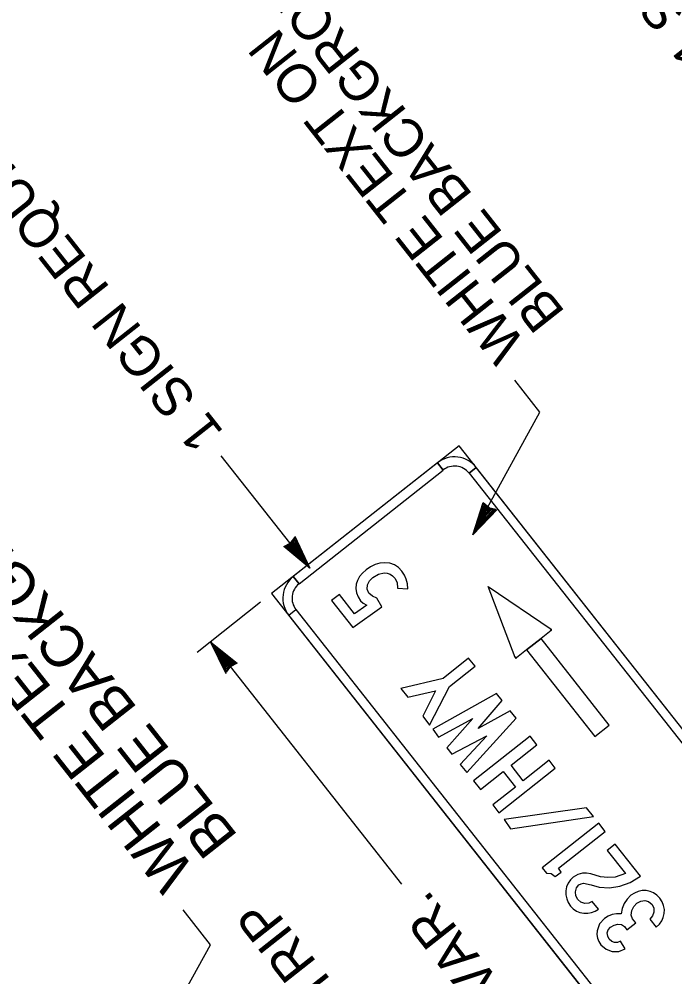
# Model space of a CAD drawing. Extents: x 671946 to 673995, y 1673066 to 1674936.
# Drawn here: x 672609.4 to 672680.8, y 1673606 to 1673710.3 of the extents above; entities that cross this region are included whole.
import ezdxf

# ---------------------------------------------------------------- set-up
doc = ezdxf.new("R2010")
doc.units = 0
doc.layers.add('C-ANNO-SYMB', color=7, linetype='Continuous')
doc.layers.add('Level 1', color=7, linetype='Continuous')

msp = doc.modelspace()

# ---------------------------------------------------------------- linework, layer by layer
at = {"layer": 'C-ANNO-SYMB'}
for p, q in [((672657.34, 1673663.83), (672636.92, 1673647.74)), ((672709.35, 1673597.87), (672657.34, 1673663.83)), ((672654.99, 1673661.98), (672639.28, 1673649.59)), ((672654.99, 1673661.98), (672655.6, 1673661.19)), ((672655.6, 1673661.19), (672654.99, 1673661.98)), ((672655.6, 1673661.19), (672654.99, 1673661.98)), ((672658.41, 1673660.86), (672659.2, 1673661.48)), ((672659.2, 1673661.48), (672658.41, 1673660.86)), ((672707.49, 1673600.22), (672659.2, 1673661.48)), ((672639.9, 1673648.81), (672655.6, 1673661.19)), ((672655.6, 1673661.19), (672655.6, 1673661.19)), ((672655.6, 1673661.19), (672655.6, 1673661.19)), ((672658.41, 1673660.86), (672706.7, 1673599.6)), ((672639.9, 1673648.81), (672639.28, 1673649.59)), ((672639.28, 1673649.59), (672639.9, 1673648.81)), ((672636.92, 1673647.74), (672688.93, 1673581.77)), ((672660.51, 1673648.5), (672660.51, 1673648.5)), ((672660.51, 1673648.5), (672660.51, 1673648.5)), ((672663.42, 1673640.78), (672660.51, 1673648.5)), ((672660.51, 1673648.5), (672667.34, 1673643.87)), ((672638.78, 1673645.38), (672639.57, 1673646)), ((672638.78, 1673645.38), (672639.57, 1673646)), ((672639.57, 1673646), (672639.57, 1673646)), ((672639.57, 1673646), (672639.57, 1673646)), ((672639.57, 1673646), (672687.86, 1673584.74)), ((672687.07, 1673584.13), (672638.78, 1673645.38)), ((672667.35, 1673643.71), (672666.25, 1673642.84)), ((672667.34, 1673643.87), (672667.29, 1673643.79)), ((672667.29, 1673643.79), (672667.34, 1673643.87)), ((672667.29, 1673643.79), (672667.35, 1673643.71)), ((672667.35, 1673643.71), (672667.29, 1673643.79)), ((672664.68, 1673641.6), (672666.25, 1673642.84)), ((672664.68, 1673641.6), (672666.25, 1673642.84)), ((672666.25, 1673642.84), (672664.68, 1673641.6)), ((672673.68, 1673633.42), (672666.25, 1673642.84)), ((672664.68, 1673641.6), (672663.58, 1673640.74)), ((672664.68, 1673641.6), (672672.11, 1673632.18)), ((672663.52, 1673640.81), (672663.42, 1673640.78)), ((672663.42, 1673640.78), (672663.52, 1673640.81)), ((672663.58, 1673640.74), (672663.52, 1673640.81)), ((672663.52, 1673640.81), (672663.58, 1673640.74)), ((672672.11, 1673632.18), (672673.68, 1673633.42)), ((672673.68, 1673633.42), (672673.68, 1673633.42)), ((672673.68, 1673633.42), (672673.68, 1673633.42))]:
    msp.add_line(p, q, dxfattribs=at)
for points in [[(672651.74, 1673648.26), (672651.7, 1673648.8), (672651.58, 1673649.3), (672651.38, 1673649.76), (672651.1, 1673650.19), (672650.72, 1673650.59), (672650.28, 1673650.87), (672649.78, 1673651.04), (672649.23, 1673651.09), (672648.71, 1673651.04), (672648.2, 1673650.9), (672647.7, 1673650.66), (672647.21, 1673650.33), (672646.81, 1673649.97), (672646.5, 1673649.59), (672646.27, 1673649.18), (672646.13, 1673648.75), (672646.09, 1673648.28), (672646.15, 1673647.83), (672646.33, 1673647.38), (672646.6, 1673646.95), (672646.89, 1673646.69), (672647.29, 1673646.49), (672645.95, 1673645.54), (672644.3, 1673647.64), (672643.45, 1673646.98), (672645.76, 1673644.04), (672648.92, 1673646.29), (672648.36, 1673647.23), (672647.89, 1673647.44), (672647.52, 1673647.78), (672647.31, 1673648.23), (672647.34, 1673648.7), (672647.57, 1673649.11), (672647.94, 1673649.49), (672648.55, 1673649.85), (672649.17, 1673649.98), (672649.51, 1673649.96), (672649.81, 1673649.86), (672650.09, 1673649.68), (672650.33, 1673649.43), (672650.58, 1673648.94), (672650.63, 1673648.34)], [(672651.75, 1673636.45), (672654.75, 1673637.15), (672653.38, 1673634.38), (672654.12, 1673633.43), (672656.28, 1673637.63), (672659.08, 1673639.83), (672658.37, 1673640.72), (672655.58, 1673638.51), (672650.99, 1673637.41)], [(672663.54, 1673634.17), (672662.89, 1673634.99), (672659.42, 1673633.07), (672662.01, 1673636.1), (672661.41, 1673636.86), (672654.46, 1673633), (672655.1, 1673632.1), (672658.84, 1673634.16), (672656, 1673630.95), (672656.55, 1673630.26), (672660.34, 1673632.25), (672657.44, 1673629.12), (672658.19, 1673628.28)], [(672667.81, 1673628.74), (672667.15, 1673629.59), (672664.32, 1673627.36), (672662.99, 1673629.05), (672665.81, 1673631.28), (672665.07, 1673632.22), (672658.91, 1673627.36), (672659.65, 1673626.42), (672662.12, 1673628.37), (672663.46, 1673626.68), (672660.99, 1673624.73), (672661.65, 1673623.89)], [(672671.97, 1673623.47), (672671.22, 1673624.42), (672662.24, 1673623.14), (672662.94, 1673622.15)], [(672673.24, 1673621.86), (672672.53, 1673622.76), (672666.37, 1673617.9), (672666.84, 1673617.31), (672667.36, 1673617.26), (672667.81, 1673616.93), (672668.46, 1673617.43), (672668.14, 1673617.84)], [(672673.46, 1673619.77), (672675.44, 1673617.26), (672674.34, 1673616.88), (672673.54, 1673616.82), (672672.73, 1673616.92), (672671.68, 1673617.22), (672671.19, 1673617.32), (672670.76, 1673617.32), (672670.27, 1673617.18), (672669.77, 1673616.87), (672669.45, 1673616.57), (672669.2, 1673616.22), (672669.04, 1673615.82), (672668.96, 1673615.39), (672668.96, 1673614.94), (672669.05, 1673614.51), (672669.21, 1673614.11), (672669.46, 1673613.73), (672669.76, 1673613.42), (672670.1, 1673613.18), (672670.48, 1673613.02), (672670.9, 1673612.94), (672671.34, 1673612.94), (672671.75, 1673613.01), (672672.14, 1673613.16), (672672.5, 1673613.38), (672671.83, 1673614.23), (672671.45, 1673614.03), (672671.01, 1673614.01), (672670.59, 1673614.15), (672670.25, 1673614.44), (672670.05, 1673614.83), (672670.01, 1673615.28), (672670.12, 1673615.71), (672670.38, 1673616.03), (672670.62, 1673616.16), (672670.87, 1673616.22), (672671.7, 1673616.05), (672672.59, 1673615.79), (672673.71, 1673615.71), (672674.82, 1673615.88), (672675.95, 1673616.31), (672677.08, 1673616.99), (672674.34, 1673620.46)], [(672678.8, 1673611.43), (672679.14, 1673611.75), (672679.39, 1673612.11), (672679.57, 1673612.5), (672679.66, 1673612.93), (672679.68, 1673613.36), (672679.6, 1673613.78), (672679.44, 1673614.18), (672679.18, 1673614.57), (672678.87, 1673614.91), (672678.51, 1673615.16), (672678.13, 1673615.33), (672677.7, 1673615.41), (672677.26, 1673615.41), (672676.84, 1673615.33), (672676.44, 1673615.15), (672676.05, 1673614.9), (672675.62, 1673614.49), (672675.3, 1673614.02), (672675.09, 1673613.48), (672674.99, 1673612.89), (672674.48, 1673612.89), (672674.01, 1673612.81), (672673.58, 1673612.64), (672673.18, 1673612.39), (672672.63, 1673611.78), (672672.36, 1673611.05), (672672.34, 1673610.64), (672672.4, 1673610.25), (672672.55, 1673609.88), (672672.78, 1673609.52), (672673.33, 1673609.02), (672674, 1673608.77), (672674.71, 1673608.78), (672675.4, 1673609.06), (672674.89, 1673609.91), (672674.59, 1673609.76), (672674.27, 1673609.75), (672673.96, 1673609.86), (672673.69, 1673610.11), (672673.51, 1673610.45), (672673.47, 1673610.81), (672673.58, 1673611.15), (672673.83, 1673611.43), (672674.2, 1673611.65), (672674.6, 1673611.76), (672675.03, 1673611.72), (672675.33, 1673611.5), (672675.61, 1673611.15), (672676.58, 1673611.91), (672676.23, 1673612.35), (672676.08, 1673612.75), (672676.15, 1673613.25), (672676.37, 1673613.69), (672676.69, 1673614.03), (672677.12, 1673614.27), (672677.54, 1673614.34), (672677.97, 1673614.22), (672678.34, 1673613.9), (672678.54, 1673613.51), (672678.55, 1673613.08), (672678.4, 1673612.66), (672678.11, 1673612.3)]]:
    msp.add_lwpolyline(points, close=True, dxfattribs=at)
for centre, radius, start, end in [((672656.84, 1673659.62), 3, 38.2506, 128.2508), ((672656.84, 1673659.62), 2, 38.2506, 128.2508), ((672641.14, 1673647.24), 3, 128.2505, 218.2508), ((672641.14, 1673647.24), 2, 128.2505, 218.2508), ((672667.29, 1673643.79), 0.1, 308.2504, 55.3534), ((672663.52, 1673640.81), 0.1, 201.148, 308.2504)]:
    msp.add_arc(centre, radius, start, end, dxfattribs=at)
at = {"layer": 'Level 1'}
for p, q in [((672641.09, 1673650.5), (672631.43, 1673662.75)), ((672658.84, 1673654.12), (672659.96, 1673657.67)), ((672658.96, 1673654.41), (672660, 1673657.52)), ((672659.19, 1673654.8), (672660.06, 1673657.36)), ((672659.36, 1673654.97), (672660.19, 1673657.13)), ((672659.38, 1673655.11), (672660.11, 1673657.24)), ((672659.96, 1673657.67), (672660.6, 1673657.1)), ((672660, 1673657.52), (672660.52, 1673657.12)), ((672660.06, 1673657.36), (672660.28, 1673657.17)), ((672660.11, 1673657.24), (672660.99, 1673656.83)), ((672660.19, 1673657.13), (672660.8, 1673656.82)), ((672660.28, 1673657.17), (672660.99, 1673656.83)), ((672660.52, 1673657.12), (672661.32, 1673656.92)), ((672661.5, 1673656.92), (672658.84, 1673654.12)), ((672661.13, 1673656.81), (672658.99, 1673654.46)), ((672661.3, 1673656.83), (672659.11, 1673654.6)), ((672660.99, 1673656.83), (672659.36, 1673654.97)), ((672660.99, 1673656.83), (672659.38, 1673655.11)), ((672659.66, 1673655.58), (672660.19, 1673656.98)), ((672660.8, 1673656.82), (672659.66, 1673655.58)), ((672660.04, 1673656.12), (672659.84, 1673655.93)), ((672659.93, 1673655.97), (672660.2, 1673656.84)), ((672660.64, 1673656.8), (672659.93, 1673655.97)), ((672660.24, 1673657.01), (672660.04, 1673656.12)), ((672660.52, 1673656.81), (672660.13, 1673656.37)), ((672660.13, 1673656.37), (672660.26, 1673656.78)), ((672660.19, 1673656.98), (672660.64, 1673656.8)), ((672660.2, 1673656.84), (672660.52, 1673656.81)), ((672660.69, 1673656.89), (672660.24, 1673657.01)), ((672660.26, 1673656.78), (672660.36, 1673656.75)), ((672660.36, 1673656.75), (672660.69, 1673656.89)), ((672660.6, 1673657.1), (672660.94, 1673656.9)), ((672660.94, 1673656.9), (672661.3, 1673656.83)), ((672661.09, 1673656.9), (672661.13, 1673656.81)), ((672659.17, 1673654.56), (672659.77, 1673655.25)), ((672659.77, 1673655.25), (672659.19, 1673654.8)), ((672659.84, 1673655.93), (672659.63, 1673655.48)), ((672659.63, 1673655.48), (672659.96, 1673655.83)), ((672639.46, 1673654), (672641.09, 1673650.5)), ((672638.23, 1673652.88), (672639, 1673653.26)), ((672638.38, 1673652.86), (672638.95, 1673653.19)), ((672638.55, 1673652.86), (672638.81, 1673652.99)), ((672638.68, 1673652.85), (672639.39, 1673653.52)), ((672638.81, 1673652.99), (672639.39, 1673653.52)), ((672638.81, 1673652.89), (672639.33, 1673653.34)), ((672639.22, 1673653.26), (672638.94, 1673652.89)), ((672638.95, 1673653.19), (672639.44, 1673653.85)), ((672638.96, 1673652.83), (672639.28, 1673653.18)), ((672639, 1673653.26), (672639.31, 1673653.49)), ((672639.08, 1673652.8), (672639.23, 1673653.07)), ((672639.23, 1673652.91), (672639.22, 1673653.26)), ((672639.23, 1673653.07), (672639.49, 1673652.55)), ((672639.28, 1673653.18), (672639.78, 1673652.21)), ((672639.31, 1673653.49), (672639.51, 1673653.8)), ((672639.33, 1673653.34), (672640.04, 1673651.82)), ((672639.44, 1673653.85), (672639.37, 1673653.63)), ((672639.37, 1673653.63), (672639.46, 1673653.64)), ((672639.39, 1673653.52), (672640.37, 1673651.38)), ((672639.39, 1673653.52), (672640.49, 1673651.3)), ((672639.46, 1673653.64), (672640.83, 1673650.77)), ((672639.51, 1673653.8), (672640.74, 1673650.93)), ((672641.09, 1673650.5), (672638.23, 1673652.88)), ((672640.86, 1673650.72), (672638.38, 1673652.86)), ((672640.59, 1673651.08), (672638.55, 1673652.86)), ((672640.37, 1673651.38), (672638.68, 1673652.85)), ((672640.49, 1673651.3), (672638.81, 1673652.89)), ((672638.94, 1673652.89), (672639.69, 1673652.37)), ((672640.04, 1673651.82), (672638.96, 1673652.83)), ((672639.78, 1673652.21), (672639.08, 1673652.8)), ((672639.16, 1673652.82), (672639.23, 1673652.91)), ((672639.49, 1673652.55), (672639.16, 1673652.82)), ((672639.69, 1673652.37), (672639.79, 1673652.12)), ((672635.71, 1673646.79), (672628.8, 1673641.34)), ((672631.95, 1673639.02), (672630.25, 1673642.48)), ((672630.25, 1673642.48), (672633.15, 1673640.16)), ((672651.09, 1673616.11), (672630.28, 1673642.51)), ((672630.61, 1673642.06), (672630.48, 1673642.26)), ((672630.48, 1673642.26), (672633.01, 1673640.18)), ((672631.94, 1673639.38), (672630.51, 1673642.22)), ((672630.51, 1673642.22), (672630.54, 1673642.01)), ((672630.54, 1673642.01), (672630.97, 1673641.22)), ((672631.9, 1673639.21), (672630.61, 1673642.06)), ((672630.97, 1673641.22), (672630.76, 1673641.91)), ((672630.76, 1673641.91), (672632.84, 1673640.18)), ((672632.01, 1673639.5), (672630.86, 1673641.69)), ((672630.86, 1673641.69), (672632.57, 1673640.14)), ((672632.01, 1673639.5), (672630.98, 1673641.62)), ((672630.98, 1673641.62), (672632.71, 1673640.18)), ((672631.58, 1673640.9), (672631.23, 1673641.26)), ((672631.23, 1673641.26), (672631.44, 1673640.82)), ((672632.07, 1673639.68), (672631.32, 1673641.19)), ((672631.32, 1673641.19), (672632.43, 1673640.19)), ((672631.68, 1673640.64), (672631.58, 1673640.9)), ((672632.11, 1673639.84), (672631.59, 1673640.8)), ((672631.59, 1673640.8), (672632.3, 1673640.23)), ((672632.44, 1673640.14), (672631.68, 1673640.64)), ((672632.15, 1673639.95), (672631.88, 1673640.47)), ((672631.88, 1673640.47), (672632.22, 1673640.2)), ((672632.08, 1673639.53), (672631.9, 1673639.21)), ((672632.03, 1673639.39), (672631.94, 1673639.38)), ((672632.44, 1673639.84), (672631.97, 1673639.17)), ((672632.71, 1673640.18), (672632.01, 1673639.5)), ((672632.58, 1673640.04), (672632.01, 1673639.5)), ((672632.57, 1673640.14), (672632.07, 1673639.68)), ((672632.39, 1673639.77), (672632.08, 1673639.53)), ((672632.43, 1673640.19), (672632.11, 1673639.84)), ((672632.3, 1673640.23), (672632.15, 1673639.95)), ((672632.22, 1673640.2), (672632.16, 1673640.12)), ((672632.16, 1673640.12), (672632.17, 1673639.76)), ((672632.17, 1673639.76), (672632.44, 1673640.14)), ((672633.15, 1673640.16), (672632.39, 1673639.77)), ((672633.01, 1673640.18), (672632.44, 1673639.84)), ((672632.84, 1673640.18), (672632.58, 1673640.04))]:
    msp.add_line(p, q, dxfattribs=at)
for points in [[(672659.98, 1673656.32), (672666.14, 1673667.5), (672663.4, 1673670.98)], [(672623.56, 1673597.34), (672630.27, 1673609.52), (672627.28, 1673613.31)]]:
    msp.add_lwpolyline(points, dxfattribs=at)

# ---------------------------------------------------------------- texts
for s, height, p in [('1 SIGN REQUIRED', 4.2, (672685.15, 1673707.36)), ('BLUE BACKGROUND', 4.2, (672668.97, 1673678.34)), ('WHITE TEXT ON', 4.2, (672664.68, 1673674.95)), ('1 SIGN REQUIRED', 4.2, (672631.79, 1673665.29)), ('BLUE BACKGROUND', 4.5747, (672633.35, 1673621.32)), ('WHITE TEXT ON', 4.5747, (672628.68, 1673617.63)), ('VAR.', 4.2, (672661.94, 1673605.33)), ('BORDER STRIP', 4.2, (672662.21, 1673581.84))]:
    msp.add_text(s, height=height, rotation=128.2505, dxfattribs=at).set_placement(p)

doc.saveas('drawing.dxf')
